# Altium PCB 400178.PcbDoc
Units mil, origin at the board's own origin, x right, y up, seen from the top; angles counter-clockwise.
Board outline 2189 x 930 mil, 2 copper layers (Top Layer, Bottom Layer), stack 12.8 mil thick; 6 components, 10 nets, 87 pads, 89 vias.
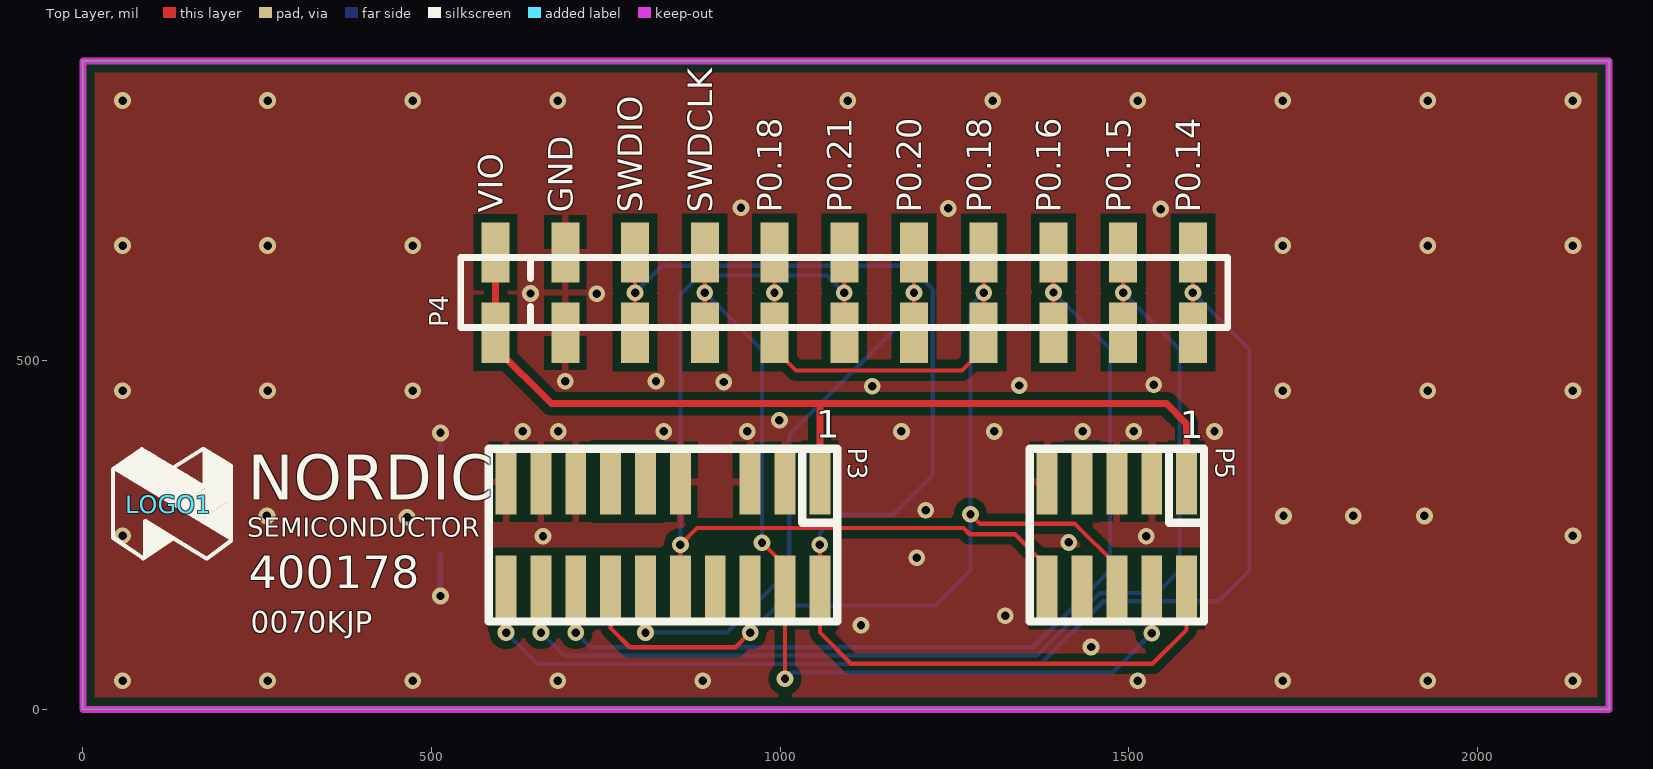
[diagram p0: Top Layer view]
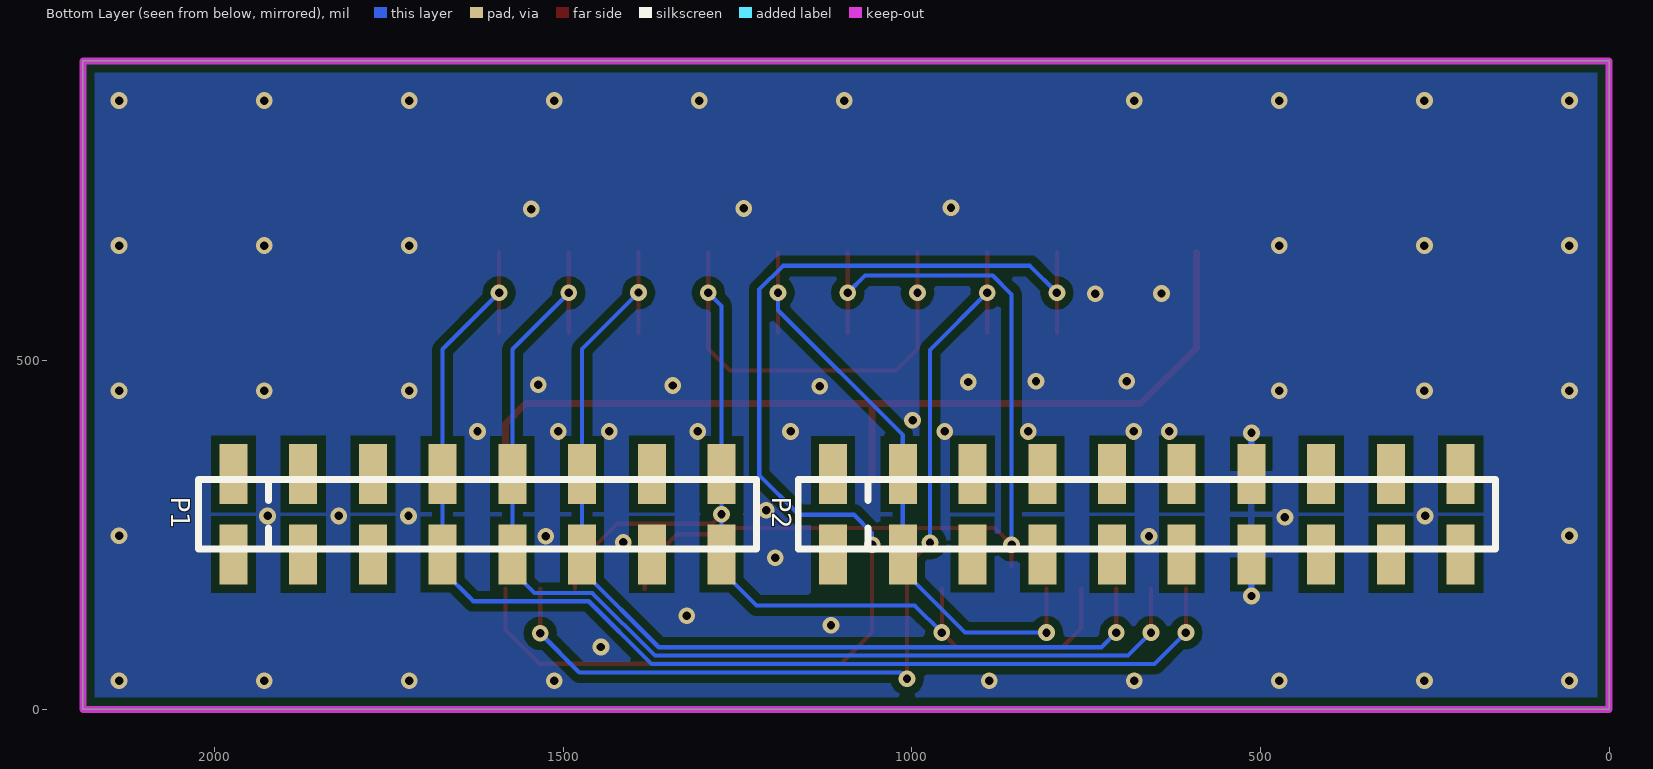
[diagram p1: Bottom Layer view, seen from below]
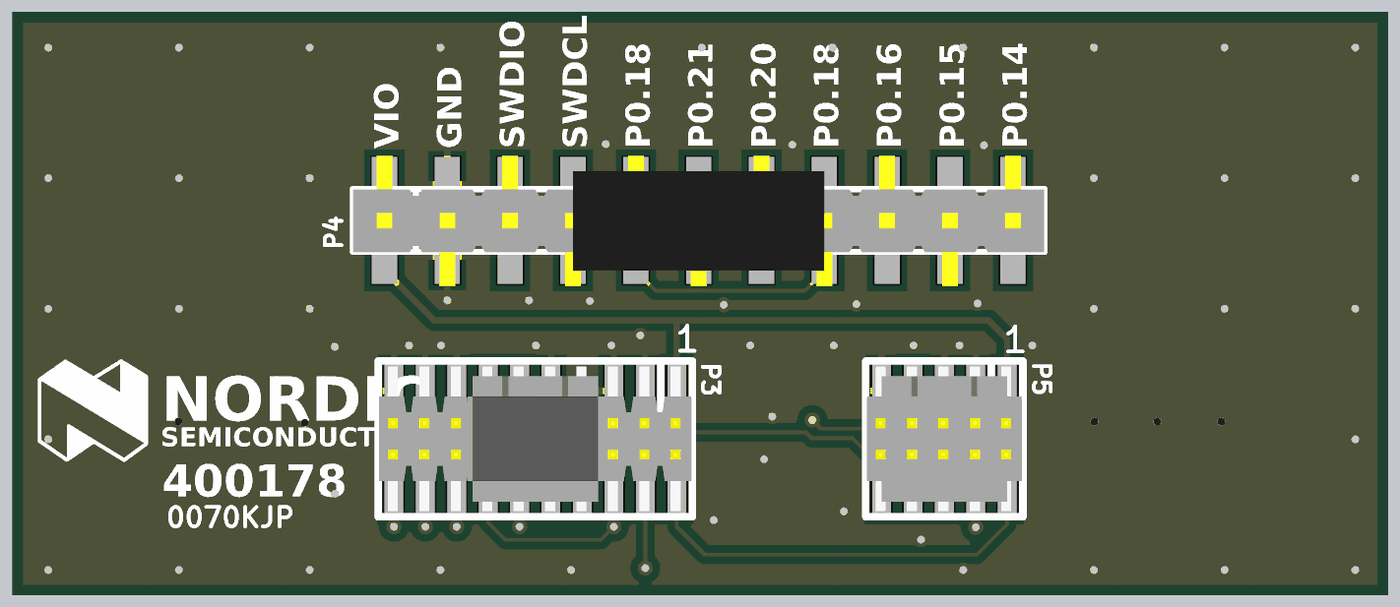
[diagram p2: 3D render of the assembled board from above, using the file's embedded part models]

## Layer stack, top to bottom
Top Solder: solder mask 0.4, Solder Resist, Dk 3.5
Top Layer: signal copper 1.4
Dielectric1: core 10, FR-4, Dk 4.2
Bottom Layer: signal copper 1.4
Bottom Solder: solder mask 0.4, Solder Resist, Dk 3.5

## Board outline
0,930 0,0 2189,0 2189,930 0,930

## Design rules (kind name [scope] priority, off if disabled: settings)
Clearance USB_Poly_Clearance [(InNamedPolygon('Top_Layer-GND')) vs (OnLayer('Mechanical 3'))] p1: gap=10
Clearance USB_Clearance [(InDifferentialPairClass('All Differential Pairs'))] p2: gap=6
Clearance ANT_Clerance [InNet('ANT') or InNet('RF')] p3: gap=6
Clearance Polygon_Clearance [(InNamedPolygon('Top_Layer-GND')) or (InNamedPolygon('Bottom_Layer-GND')) or (InNamedPolygon('Mid_Layer_1-GND')) or (InNamedPolygon('Mid_Layer_2-VDD_3V3')) or (InNamedPolygon('Mid_Layer_2-VIO'))] p4: gap=12
Clearance SB_Clearance [HasFootprint('Solderbridge') or HasFootprint('QFN40P180X140X55-10N')] p5: gap=5
Clearance CSP_Clearance [HasFootprint('LGA-16 (3x3x1.0mm)')] p6: gap=5
Clearance [All] p7: gap=6
ComponentClearance [All] p1 off: gap=10 collisioncheckmode=3 verticalgap=10 showdistances=FALSE
DiffPairsRouting [All] p1: maxlimit=5.91 minlimit=5.91 mostfreqgap=5.91 toplayer_minwidth=8 toplayer_maxwidth=15 toplayer_prefwidth=15 bottomlayer_minwidth=8 bottomlayer_maxwidth=15 bottomlayer_prefwidth=15 maxuncoupledlength=500
FabricationTestPointUsage TestPointUsage [All] p1: valid=0 allowmultiple=FALSE
FabricationTestpoint Testpoint [All] p1: side=3 testpointundercomponent=TRUE minsize=40 maxsize=100 preferedsize=60 minholesize=0 maxholesize=40 preferedholesize=32 testpointgrid=1 allowsidetop=TRUE allowsidebottom=TRUE usegrid=TRUE gridtolerance=0.01
Height [All] p1 off: minheight=0 maxheight=1000 prefheight=500
HoleSize [All] p1: absolutevalues=TRUE maxlimit=196.85 minlimit=12 maxpercent=80.000 minpercent=20.000
MinimumAnnularRing [All] p1 off: minimumring=6
PolygonConnect PolygonConnect_1 [isVia and innet(gnd)] p1: connectstyle=Direct reliefconductorwidth=10 reliefentries=4 polygonreliefangle="90 Angle" airgapwidth=10
PolygonConnect [All] p2: connectstyle=Relief reliefconductorwidth=10 reliefentries=4 polygonreliefangle="90 Angle" airgapwidth=10
RoutingVias [All] p1: holewidth=12 width=24 viastyle="Through Hole" minholewidth=12 minwidth=24 maxholewidth=28 maxwidth=50
ShortCircuit ShortCircuit_1 [InNet('VCC_IO') vs InNet('NetSB8_2')] p1: allowed=TRUE
ShortCircuit ShortCircuit_2 [InNet('VCC_nRF') vs InNet('V3')] p2: allowed=TRUE
ShortCircuit [All] p3: allowed=FALSE
SilkToSolderMaskClearance SilkscreenOverComponentPads [IsPad] p1: minsilkscreentomaskgap=10 clearancetoexposedcopper=TRUE
SolderMaskExpansion [All] p1: expansion=3
Width [All] p1: maxlimit=100 minlimit=6 preferedwidth=6
22 further rules are at their usual default settings.

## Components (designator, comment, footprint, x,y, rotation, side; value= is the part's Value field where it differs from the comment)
LOGO1 "Nordic Logo M" NORDIC_LOGO_M 123,294 r0 top
P1 "Pin List 1x8" LIST_1x8_SMD 1973,279.74 r180 bottom (schematic designator IOL)
P2 "Pin List 1x10" LIST_1x10_SMD 1113,279.74 r180 bottom (schematic designator IOH)
P3 "FTSH-110 SWD" FTSH-110-K-SWD 832,249.77 r180 top
P4 "Pin List 1x11" LIST_1x11_SMD 592,540 r0 top
P5 "FTSH-105" FTSH-105-K 1483,249.77 r180 top

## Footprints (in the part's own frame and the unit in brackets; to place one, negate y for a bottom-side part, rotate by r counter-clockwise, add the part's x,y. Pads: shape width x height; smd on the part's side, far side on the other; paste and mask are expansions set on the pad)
FTSH-105-K [mm] "SMT MICRO HEADER, (1,27) .050\" Keying Shroud"
  rect 0.76x2.4 smd: 1(-2.54,-1.95) 2(-2.54,1.95) 3(-1.27,-1.95) 4(-1.27,1.95) 5(0,-1.95) 6(0,1.95) 7(1.27,-1.95) 8(1.27,1.95) 9(2.54,-1.95) 10(2.54,1.95)
  silkscreen extent -3.18,-3.15 3.18,3.15, body extent -3.14,-2.92 3.14,2.92, height 6.11
FTSH-110-K-SWD [mm] "SMT MICRO HEADER, (1,27) .050\" Keying Shroud w/ pin 7 removed"
  rect 0.76x2.4 smd: 1(-5.715,-1.95) 2(-5.715,1.95) 3(-4.445,-1.95) 4(-4.445,1.95) 5(-3.175,-1.95) 6(-3.175,1.95) 8(-1.905,1.95) 9(-0.635,-1.95) 10(-0.635,1.95) 11(0.635,-1.95) 12(0.635,1.95) 13(1.905,-1.95) 14(1.905,1.95) 15(3.175,-1.95) 16(3.175,1.95) 17(4.445,-1.95) 18(4.445,1.95) 19(5.715,-1.95) 20(5.715,1.95)
  silkscreen extent -6.35,-3.15 6.35,3.15, body extent -6.31,-2.92 6.31,2.92, height 6.98
LIST_1x8_SMD [mm] "Pin List, 2.54mm, SMD"
  rect 1.02x2.19 smd: 1(0,-1.465) 1(0,1.465) 2(2.54,-1.465) 2(2.54,1.465) 3(5.08,-1.465) 3(5.08,1.465) 4(7.62,-1.465) 4(7.62,1.465) 5(10.16,-1.465) 5(10.16,1.465) 6(12.7,-1.465) 6(12.7,1.465) 7(15.24,-1.465) 7(15.24,1.465) 8(17.78,-1.465) 8(17.78,1.465)
  silkscreen extent -1.27,-1.27 19.05,1.27, body extent -1.27,-2.5 19.05,2.5, height 9.82
LIST_1x10_SMD [mm] "Pin List, 2.54mm, SMD"
  rect 1.02x2.19 smd: 1(0,-1.465) 1(0,1.465) 2(2.54,-1.465) 2(2.54,1.465) 3(5.08,-1.465) 3(5.08,1.465) 4(7.62,-1.465) 4(7.62,1.465) 5(10.16,-1.465) 5(10.16,1.465) 6(12.7,-1.465) 6(12.7,1.465) 7(15.24,-1.465) 7(15.24,1.465) 8(17.78,-1.465) 8(17.78,1.465) 9(20.32,-1.465) 9(20.32,1.465) 10(22.86,-1.465) 10(22.86,1.465)
  silkscreen extent -1.27,-1.27 24.13,1.27, body extent -1.27,-2.5 24.13,2.5, height 9.82
LIST_1x11_SMD [mm] "Pin List, 2.54mm, SMD"
  rect 1.02x2.19 smd: 1(0,0) 1(0,2.93) 2(2.54,0) 2(2.54,2.93) 3(5.08,0) 3(5.08,2.93) 4(7.62,0) 4(7.62,2.93) 5(10.16,0) 5(10.16,2.93) 6(12.7,0) 6(12.7,2.93) 7(15.24,0) 7(15.24,2.93) 8(17.78,0) 8(17.78,2.93) 9(20.32,0) 9(20.32,2.93) 10(22.86,0) 10(22.86,2.93) 11(25.4,0) 11(25.4,2.93)
  silkscreen extent -1.27,0.2 26.67,2.74, body extent -1.27,-1.19 26.67,4.09, height 22.38
NORDIC_LOGO_M [mil] "Medium Nordic Logo"
  silkscreen extent -80,-78 90,80

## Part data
LOGO1: "Nordic Logo, medium size"
P1: library part "Pin List 1x8 SMD", "Pin List 1x8, 2.54mm (100mil), SMD"
P2: library part "Pin List 1x10 SMD", "Pin List 1x10, 2.54mm (100mil), SMD"
P3: library part "Samtec FTSH-110 SWD Keying Shroud", "SAMTEC - CONN HEADER 20POS DUAL .05\" SMD KEYING SHROUD Removed Pin 7"
P4: library part "Pin List 1x11 SMD", "Pin List 1x11, 2.54mm (100mil), SMD"
P5: library part "Samtec FTSH-105 Keying Shroud", "SAMTEC - CONN HEADER 10POS DUAL .05\" SMD KEYING SHROUD"

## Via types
v1: diameter 24, hole 12, Top Layer to Bottom Layer, tented both sides, 89 vias

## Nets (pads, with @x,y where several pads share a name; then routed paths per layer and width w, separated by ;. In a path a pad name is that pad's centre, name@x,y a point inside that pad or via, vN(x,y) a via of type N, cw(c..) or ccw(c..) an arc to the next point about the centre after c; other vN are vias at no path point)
GND: P2.7 P3.3 P3.5 P3.9 P3.15 P3.17 P3.19 P4.2 P5.3 P5.5 P5.9 | length 118.6
  Bottom Layer w9: v1(513,162.42) P2.7@513,222.06 ; P2.7@513,337.42 v1(513,396.42)
  other v1: 57,41 265,41 473,41 681,41 889,41 1513,41 1721,41 1929,41 2137,41 1446,89.35 1116,120.35 1323,134.35 1196,217.35 1414,239.35 660,248.35 1525,248.35 57,249 2137,249 465,275.35 264,277.35 1722,277.35 1822,277.35 1924,277.35 1209,285.35 631,398.54 682,398.54 833,398.54 953,398.54 1174,398.54 1307,398.54 1434,398.54 1507,398.54 1623,398.54 999,414.54 57,457 265,457 473,457 1721,457 1929,457 2137,457 1132,463.35 1343,464.35 1536,465.35 919,469.35 692,470.54 822,470.35 642,596.35 737,596 57,665 265,665 473,665 1721,665 1929,665 2137,665 1546,717.35 1241,718.35 944,719.35 57,873 265,873 473,873 681,873 1097,873 1305,873 1513,873 1721,873 1929,873 2137,873
P0.14: P1.4 P3.20 P4.11 | length 1750.4
  Top Layer w6: v1(607,110) P3.20 ; P4.11@1592,540 v1(1592,597.35) P4.11@1592,655.35
  Bottom Layer w6: v1(607,110) 652,65 1373.51,65 1463.51,155 1629,155 1673,199 1673,337.42 1673,516.36 v1(1592,597.35)
P0.15: P1.5 P3.18 P4.10 | length 1590.5
  Top Layer w6: v1(657,110) P3.18 ; P4.10@1492,540 v1(1492,597.35) P4.10@1492,655.35
  Bottom Layer w6: v1(657,110) 690,77 1368.54,77 1458.54,167 1541,167 1573,199 1573,222.06 1573,337.42 1573,516.36 v1(1492,597.35)
P0.16: P1.6 P3.16 P4.9 | length 1430.8
  Top Layer w6: v1(707,110) P3.16 ; P4.9@1392,540 v1(1392,597.68) P4.9@1392,655.35
  Bottom Layer w6: v1(707,110) 728,89 1363,89 1473,199 1473,222.06 1473,337.42 1473,516.68 v1(1392,597.68)
P0.18: P1.8 P3.6 P3.14 P4.5 P4.8 P5.6 | length 1974.7
  Top Layer w6: P3.14 757,116.35 784.35,89 936,89 v1(957,110) P3.6 ; P4.5@992,655.35 v1(992,597.35) 992,540 992,517 1023,486 1261,486 1292,517 1292,540 v1(1292,597.35) P4.8@1292,655.35 ; v1(1273,279.74) 1286.74,266 1423,266 1483,206 P5.6
  Bottom Layer w6: v1(957,110) 996,149 1223,149 1273,199 1273,222.06 v1(1273,279.74) 1273,337.42 1273,578.35 v1(1292,597.35)
P0.20: P2.2 P3.12 P4.7 | length 893.7
  Top Layer w6: v1(807,110) P3.12 ; P4.7@1192,540 v1(1192,597.35) P4.7@1192,655.35
  Bottom Layer w6: v1(807,110) 924,110 1013,199 1013,222.06 1013,337.42 1013,393.35 1192,572.35 v1(1192,597.35)
P0.21: P3.10 P4.6 P5.10 | length 1352.5
  Top Layer w6: P3.10@857,205 v1(857,236) 881,260 1263,260 1272,251 1337,251 1383,205 P5.10 ; P4.6@1092,540 P4.6@1092,655.35
  Bottom Layer w6: v1(857,236) 857,595 884,622 1067.35,622 v1(1092,597.35)
SWDCLK: P3.4 P4.4 P5.4 | length 1333.3
  Top Layer w6: P4.4@892,540 v1(892,597.35) P4.4@892,655.35 ; v1(974,239) 1007,206 P3.4 v1(1007,44) ; v1(1533,109) P5.4
  Bottom Layer w6: v1(892,597.35) 974,515.35 v1(974,239) ; v1(1007,44) 1016,53 1477,53 v1(1533,109)
SWDIO: P3.2 P4.3 P5.2 | length 1801.5
  Top Layer w6: P4.3@792,540 v1(792,597.35) P4.3@792,655.35 ; v1(1057,236) P3.2 1057,110 1101.65,65.35 1534.35,65.35 1583,114 P5.2
  Bottom Layer w6: v1(792,597.35) 830.65,636 1185,636 1219,602 1219,336 1162,279 1083,279 1057,253 v1(1057,236)
VIO: P3.1 P4.1 P5.1 | length 1367.8
  Top Layer w10: P4.1@592,655.35 592,540 592,518.36 672,438.35 1057,438.35 ; P3.1 1057,438.35 ; P5.1 1583,409.36 1554,438.35 1057,438.35
pads on no net: P1.1 P1.2 P1.3 P1.7 P2.1 P2.3 P2.4 P2.5 P2.6 P2.8 P2.9 P2.10 P3.8 P3.11 P3.13 P5.7 P5.8

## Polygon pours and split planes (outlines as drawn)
GND on Top Layer "Top_Layer-GND" (solid, remove dead copper, pour order 8): -125,-132 -125,1004 2391,1004 2391,-132
GND on Bottom Layer "Bottom_Layer-GND" (solid, remove dead copper, pour order 6): -132,-137 -132,1005 2404,1005 2404,-137

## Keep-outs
Keep-Out Layer:
  the board outline again, w10

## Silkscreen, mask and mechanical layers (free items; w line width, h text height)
Top Overlay:
  text "VIO" at 614,712 h60 r90
  text "GND" at 714,712 h60 r90
  text "SWDIO" at 814,712 h60 r90
  text "SWDCLK" at 914,712 h60 r90
  text "P0.18" at 1014,712 h60 r90
  text "P0.21" at 1114,712 h60 r90
  text "P0.20" at 1214,712 h60 r90
  text "P0.18" at 1314,712 h60 r90
  text "P0.16" at 1414,712 h60 r90
  text "P0.15" at 1514,712 h60 r90
  text "P0.14" at 1614,712 h60 r90
  text "NORDIC" at 236.67,278.92 h110
  text "SEMICONDUCTOR" at 235.67,237.92 h47
  text "400178" at 238,158 h80
  text "0070KJP" at 241,110.03 h31
Mechanical 1:
  the board outline again, w10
